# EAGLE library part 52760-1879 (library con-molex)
MOLEX Connector SD-52760-**79 Source: 52760-1079_sd molex.pdf
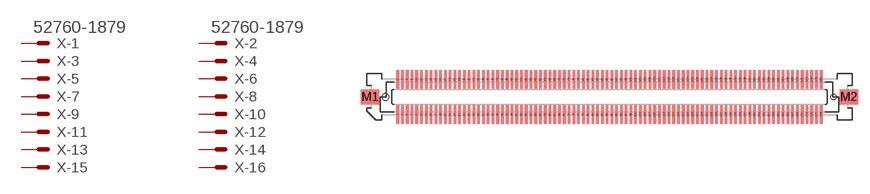
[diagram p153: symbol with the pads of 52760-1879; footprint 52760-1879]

Designator prefix X; gates -1=MV -2=MV -3=M -4=M -5=M -6=M -7=M -8=M -9=M -10=M -11=M -12=M -13=M -14=M -15=M -16=M -17=M -18=M -19=M -20=M -21=M -22=M -23=M -24=M -25=M -26=M -27=M -28=M -29=M -30=M -31=M -32=M -33=M -34=M -35=M -36=M -37=M -38=M -39=M -40=M -41=M -42=M -43=M -44=M -45=M -46=M -47=M -48=M -49=M -50=M -51=M -52=M -53=M -54=M -55=M -56=M -57=M -58=M -59=M -60=M -61=M -62=M -63=M -64=M -65=M -66=M -67=M -68=M -69=M -70=M -71=M -72=M -73=M -74=M -75=M -76=M -77=M -78=M -79=M -80=M -81=M -82=M -83=M -84=M -85=M -86=M -87=M -88=M -89=M -90=M -91=M -92=M -93=M -94=M -95=M -96=M -97=M -98=M -99=M -100=M -101=M -102=M -103=M -104=M -105=M -106=M -107=M -108=M -109=M -110=M -111=M -112=M -113=M -114=M -115=M -116=M -117=M -118=M -119=M -120=M -121=M -122=M -123=M -124=M -125=M -126=M -127=M -128=M -129=M -130=M -131=M -132=M -133=M -134=M -135=M -136=M -137=M -138=M -139=M -140=M -141=M -142=M -143=M -144=M -145=M -146=M -147=M -148=M -149=M -150=M -151=M -152=M -153=M -154=M -155=M -156=M -157=M -158=M -159=M -160=M -161=M -162=M -163=M -164=M -165=M -166=M -167=M -168=M -169=M -170=M -171=M -172=M -173=M -174=M -175=M -176=M -177=M -178=M -179=M -180=M

## 52760-1879 (MPN: 52760-1879; OC_FARNELL: unknown; OC_NEWARK: 92M6435)  [52760-1879]
1  -1:S  pas
2  -2:S  pas
3  -3:S  pas
4  -4:S  pas
5  -5:S  pas
6  -6:S  pas
7  -7:S  pas
8  -8:S  pas
9  -9:S  pas
10  -10:S  pas
11  -11:S  pas
12  -12:S  pas
13  -13:S  pas
14  -14:S  pas
15  -15:S  pas
16  -16:S  pas
17  -17:S  pas
18  -18:S  pas
19  -19:S  pas
20  -20:S  pas
21  -21:S  pas
22  -22:S  pas
23  -23:S  pas
24  -24:S  pas
25  -25:S  pas
26  -26:S  pas
27  -27:S  pas
28  -28:S  pas
29  -29:S  pas
30  -30:S  pas
31  -31:S  pas
32  -32:S  pas
33  -33:S  pas
34  -34:S  pas
35  -35:S  pas
36  -36:S  pas
37  -37:S  pas
38  -38:S  pas
39  -39:S  pas
40  -40:S  pas
41  -41:S  pas
42  -42:S  pas
43  -43:S  pas
44  -44:S  pas
45  -45:S  pas
46  -46:S  pas
47  -47:S  pas
48  -48:S  pas
49  -49:S  pas
50  -50:S  pas
51  -51:S  pas
52  -52:S  pas
53  -53:S  pas
54  -54:S  pas
55  -55:S  pas
56  -56:S  pas
57  -57:S  pas
58  -58:S  pas
59  -59:S  pas
60  -60:S  pas
61  -61:S  pas
62  -62:S  pas
63  -63:S  pas
64  -64:S  pas
65  -65:S  pas
66  -66:S  pas
67  -67:S  pas
68  -68:S  pas
69  -69:S  pas
70  -70:S  pas
71  -71:S  pas
72  -72:S  pas
73  -73:S  pas
74  -74:S  pas
75  -75:S  pas
76  -76:S  pas
77  -77:S  pas
78  -78:S  pas
79  -79:S  pas
80  -80:S  pas
81  -81:S  pas
82  -82:S  pas
83  -83:S  pas
84  -84:S  pas
85  -85:S  pas
86  -86:S  pas
87  -87:S  pas
88  -88:S  pas
89  -89:S  pas
90  -90:S  pas
91  -91:S  pas
92  -92:S  pas
93  -93:S  pas
94  -94:S  pas
95  -95:S  pas
96  -96:S  pas
97  -97:S  pas
98  -98:S  pas
99  -99:S  pas
100  -100:S  pas
101  -101:S  pas
102  -102:S  pas
103  -103:S  pas
104  -104:S  pas
105  -105:S  pas
106  -106:S  pas
107  -107:S  pas
108  -108:S  pas
109  -109:S  pas
110  -110:S  pas
111  -111:S  pas
112  -112:S  pas
113  -113:S  pas
114  -114:S  pas
115  -115:S  pas
116  -116:S  pas
117  -117:S  pas
118  -118:S  pas
119  -119:S  pas
120  -120:S  pas
121  -121:S  pas
122  -122:S  pas
123  -123:S  pas
124  -124:S  pas
125  -125:S  pas
126  -126:S  pas
127  -127:S  pas
128  -128:S  pas
129  -129:S  pas
130  -130:S  pas
131  -131:S  pas
132  -132:S  pas
133  -133:S  pas
134  -134:S  pas
135  -135:S  pas
136  -136:S  pas
137  -137:S  pas
138  -138:S  pas
139  -139:S  pas
140  -140:S  pas
141  -141:S  pas
142  -142:S  pas
143  -143:S  pas
144  -144:S  pas
145  -145:S  pas
146  -146:S  pas
147  -147:S  pas
148  -148:S  pas
149  -149:S  pas
150  -150:S  pas
151  -151:S  pas
152  -152:S  pas
153  -153:S  pas
154  -154:S  pas
155  -155:S  pas
156  -156:S  pas
157  -157:S  pas
158  -158:S  pas
159  -159:S  pas
160  -160:S  pas
161  -161:S  pas
162  -162:S  pas
163  -163:S  pas
164  -164:S  pas
165  -165:S  pas
166  -166:S  pas
167  -167:S  pas
168  -168:S  pas
169  -169:S  pas
170  -170:S  pas
171  -171:S  pas
172  -172:S  pas
173  -173:S  pas
174  -174:S  pas
175  -175:S  pas
176  -176:S  pas
177  -177:S  pas
178  -178:S  pas
179  -179:S  pas
180  -180:S  pas

## Footprint 52760-1879 (pad centres in mm)
MOLEX Connector SD-52760-**79 Source: 52760-1079_sd molex.pdf
smd 0.35 x 2.5: 1 -28.258,-2.35; 2 -28.258,2.35; 3 -27.622,-2.35; 4 -27.622,2.35; 5 -26.988,-2.35; 6 -26.988,2.35; 7 -26.352,-2.35; 8 -26.352,2.35; 9 -25.718,-2.35; 10 -25.718,2.35; 11 -25.082,-2.35; 12 -25.082,2.35; 13 -24.448,-2.35; 14 -24.448,2.35; 15 -23.812,-2.35; 16 -23.812,2.35; 17 -23.177,-2.35; 18 -23.177,2.35; 19 -22.543,-2.35; 20 -22.543,2.35; 21 -21.907,-2.35; 22 -21.907,2.35; 23 -21.273,-2.35; 24 -21.273,2.35; 25 -20.637,-2.35; 26 -20.637,2.35; 27 -20.003,-2.35; 28 -20.003,2.35; 29 -19.367,-2.35; 30 -19.367,2.35; 31 -18.733,-2.35; 32 -18.733,2.35; 33 -18.098,-2.35; 34 -18.098,2.35; 35 -17.462,-2.35; 36 -17.462,2.35; 37 -16.828,-2.35; 38 -16.828,2.35; 39 -16.192,-2.35; 40 -16.192,2.35; 41 -15.557,-2.35; 42 -15.557,2.35; 43 -14.922,-2.35; 44 -14.922,2.35; 45 -14.287,-2.35; 46 -14.287,2.35; 47 -13.652,-2.35; 48 -13.652,2.35; 49 -13.018,-2.35; 50 -13.018,2.35; 51 -12.383,-2.35; 52 -12.383,2.35; 53 -11.748,-2.35; 54 -11.748,2.35; 55 -11.113,-2.35; 56 -11.113,2.35; 57 -10.477,-2.35; 58 -10.477,2.35; 59 -9.842,-2.35; 60 -9.842,2.35; 61 -9.207,-2.35; 62 -9.207,2.35; 63 -8.572,-2.35; 64 -8.572,2.35; 65 -7.938,-2.35; 66 -7.938,2.35; 67 -7.303,-2.35; 68 -7.303,2.35; 69 -6.668,-2.35; 70 -6.668,2.35; 71 -6.032,-2.35; 72 -6.032,2.35; 73 -5.397,-2.35; 74 -5.397,2.35; 75 -4.763,-2.35; 76 -4.763,2.35; 77 -4.128,-2.35; 78 -4.128,2.35; 79 -3.493,-2.35; 80 -3.493,2.35; 81 -2.857,-2.35; 82 -2.857,2.35; 83 -2.223,-2.35; 84 -2.223,2.35; 85 -1.587,-2.35; 86 -1.587,2.35; 87 -0.953,-2.35; 88 -0.953,2.35; 89 -0.318,-2.35; 90 -0.318,2.35; 91 0.318,-2.35; 92 0.318,2.35; 93 0.953,-2.35; 94 0.953,2.35; 95 1.587,-2.35; 96 1.587,2.35; 97 2.223,-2.35; 98 2.223,2.35; 99 2.857,-2.35; 100 2.857,2.35; 101 3.493,-2.35; 102 3.493,2.35; 103 4.128,-2.35; 104 4.128,2.35; 105 4.763,-2.35; 106 4.763,2.35; 107 5.397,-2.35; 108 5.397,2.35; 109 6.032,-2.35; 110 6.032,2.35; 111 6.668,-2.35; 112 6.668,2.35; 113 7.303,-2.35; 114 7.303,2.35; 115 7.938,-2.35; 116 7.938,2.35; 117 8.572,-2.35; 118 8.572,2.35; 119 9.207,-2.35; 120 9.207,2.35; 121 9.842,-2.35; 122 9.842,2.35; 123 10.477,-2.35; 124 10.477,2.35; 125 11.113,-2.35; 126 11.113,2.35; 127 11.748,-2.35; 128 11.748,2.35; 129 12.383,-2.35; 130 12.383,2.35; 131 13.018,-2.35; 132 13.018,2.35; 133 13.652,-2.35; 134 13.652,2.35; 135 14.287,-2.35; 136 14.287,2.35; 137 14.922,-2.35; 138 14.922,2.35; 139 15.557,-2.35; 140 15.557,2.35; 141 16.192,-2.35; 142 16.192,2.35; 143 16.828,-2.35; 144 16.828,2.35; 145 17.462,-2.35; 146 17.462,2.35; 147 18.098,-2.35; 148 18.098,2.35; 149 18.733,-2.35; 150 18.733,2.35; 151 19.367,-2.35; 152 19.367,2.35; 153 20.003,-2.35; 154 20.003,2.35; 155 20.637,-2.35; 156 20.637,2.35; 157 21.273,-2.35; 158 21.273,2.35; 159 21.907,-2.35; 160 21.907,2.35; 161 22.543,-2.35; 162 22.543,2.35; 163 23.177,-2.35; 164 23.177,2.35; 165 23.812,-2.35; 166 23.812,2.35; 167 24.448,-2.35; 168 24.448,2.35; 169 25.082,-2.35; 170 25.082,2.35; 171 25.718,-2.35; 172 25.718,2.35; 173 26.352,-2.35; 174 26.352,2.35; 175 26.988,-2.35; 176 26.988,2.35; 177 27.622,-2.35; 178 27.622,2.35; 179 28.258,-2.35; 180 28.258,2.35
smd 2.5 x 2: M1 -31.95,0; M2 31.95,0
hole 0.9 at -29.91,0
hole 0.7 at 29.91,0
